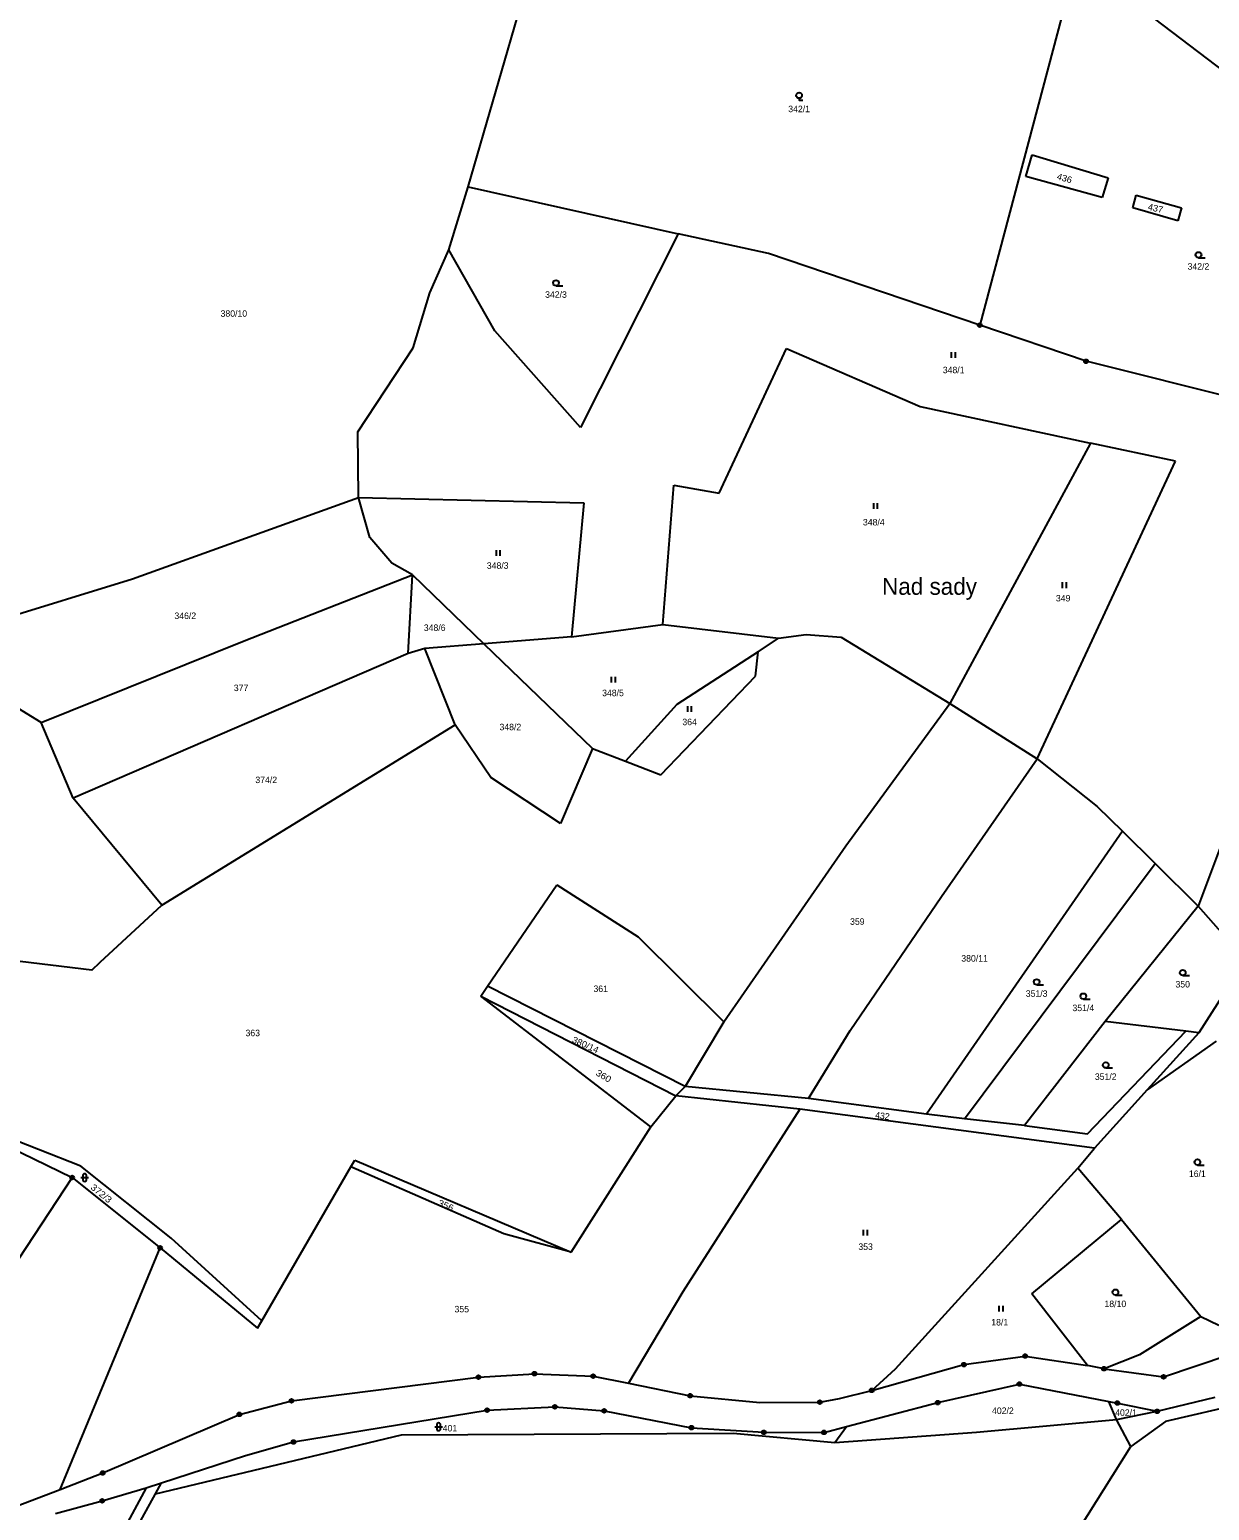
# Model space of a CAD drawing. Extents: x -791548 to -789311, y -1142631 to -1140855.
# Drawn here: x -790753.3 to -790444.3, y -1142346.8 to -1141959 of the extents above; entities that cross this region are included whole.
import ezdxf
from ezdxf.enums import TextEntityAlignment as Align

# ---------------------------------------------------------------- set-up
doc = ezdxf.new("R2010")
doc.units = 0
doc.header["$LTSCALE"] = 0.68
for name, color, linetype, lineweight in [('1', 7, 'Continuous', 25), ('3', 7, 'Continuous', 25), ('7', 7, 'Continuous', 13), ('8', 7, 'Continuous', 25)]:
    doc.layers.add(name, color=color, linetype=linetype, lineweight=lineweight)
doc.layers.add('2', color=7, linetype='Continuous')

msp = doc.modelspace()

# ---------------------------------------------------------------- linework, layer by layer
at = {"layer": '1'}
for p, q in [((-790479.88, -1141943.84), (-790504.47, -1142036.41)), ((-790638.46, -1142000.15), (-790623.72, -1141949.45)), ((-790465.97, -1141950.58), (-790409.55, -1141993.58)), ((-790492.43, -1141997.44), (-790490.72, -1141991.84)), ((-790490.72, -1141991.84), (-790470.82, -1141997.82)), ((-790472.36, -1142003), (-790492.43, -1141997.44)), ((-790470.82, -1141997.82), (-790472.36, -1142003)), ((-790643.5, -1142016.71), (-790638.46, -1142000.15)), ((-790638.46, -1142000.15), (-790583.42, -1142012.45)), ((-790464.34, -1142005.66), (-790463.47, -1142002.34)), ((-790463.47, -1142002.34), (-790451.66, -1142005.71)), ((-790452.58, -1142009.07), (-790464.34, -1142005.66)), ((-790451.66, -1142005.71), (-790452.58, -1142009.07)), ((-790583.42, -1142012.45), (-790609.02, -1142063.22)), ((-790559.75, -1142017.62), (-790583.42, -1142012.45)), ((-790648.46, -1142027.96), (-790643.5, -1142016.71)), ((-790631.41, -1142037.87), (-790643.5, -1142016.71)), ((-790504.47, -1142036.41), (-790559.75, -1142017.62)), ((-790652.8, -1142042.31), (-790648.46, -1142027.96)), ((-790609.02, -1142063.22), (-790631.41, -1142037.87)), ((-790476.62, -1142045.87), (-790504.47, -1142036.41)), ((-790667.36, -1142064.38), (-790652.8, -1142042.31)), ((-790572.66, -1142080.37), (-790555.04, -1142042.51)), ((-790555.04, -1142042.51), (-790520.07, -1142057.67)), ((-790406.17, -1142063.5), (-790476.62, -1142045.87)), ((-790520.07, -1142057.67), (-790475.49, -1142067.34)), ((-790667.17, -1142081.58), (-790667.36, -1142064.38)), ((-790475.49, -1142067.34), (-790512.31, -1142135.46)), ((-790453.23, -1142072.06), (-790475.49, -1142067.34)), ((-790489.4, -1142150.03), (-790453.23, -1142072.06)), ((-790587.41, -1142114.84), (-790584.55, -1142078.32)), ((-790584.55, -1142078.32), (-790572.66, -1142080.37)), ((-790726.36, -1142102.85), (-790667.17, -1142081.58)), ((-790667.17, -1142081.58), (-790608.11, -1142082.9)), ((-790664.16, -1142091.98), (-790667.17, -1142081.58)), ((-790608.11, -1142082.9), (-790611.38, -1142118.03)), ((-790658.38, -1142098.74), (-790664.16, -1142091.98)), ((-790653.02, -1142101.76), (-790658.38, -1142098.74)), ((-790783.03, -1142120.37), (-790726.36, -1142102.85)), ((-790697.06, -1142119.11), (-790653.02, -1142101.76)), ((-790654.16, -1142122.43), (-790653.02, -1142101.76)), ((-790653.02, -1142101.76), (-790634.32, -1142119.84)), ((-790415.68, -1142104.15), (-790447.27, -1142188.54)), ((-790611.38, -1142118.03), (-790587.41, -1142114.84)), ((-790587.41, -1142114.84), (-790557.12, -1142118.38)), ((-790750.26, -1142140.45), (-790697.06, -1142119.11)), ((-790611.38, -1142118.03), (-790634.32, -1142119.84)), ((-790562.48, -1142121.95), (-790557.12, -1142118.38)), ((-790557.12, -1142118.38), (-790549.88, -1142117.43)), ((-790549.88, -1142117.43), (-790540.77, -1142118.16)), ((-790540.77, -1142118.16), (-790512.31, -1142135.46)), ((-790750.26, -1142140.45), (-790783.03, -1142120.37)), ((-790649.81, -1142121.06), (-790654.16, -1142122.43)), ((-790634.32, -1142119.84), (-790649.81, -1142121.06)), ((-790641.86, -1142141.11), (-790649.81, -1142121.06)), ((-790634.32, -1142119.84), (-790605.89, -1142147.32)), ((-790562.48, -1142121.95), (-790583.81, -1142135.76)), ((-790563.14, -1142128.33), (-790562.48, -1142121.95)), ((-790587.98, -1142154.17), (-790563.14, -1142128.33)), ((-790583.81, -1142135.76), (-790597.25, -1142150.63)), ((-790539.56, -1142172.74), (-790512.31, -1142135.46)), ((-790512.31, -1142135.46), (-790489.4, -1142150.03)), ((-790718.67, -1142188.35), (-790641.86, -1142141.11)), ((-790632.48, -1142154.84), (-790641.86, -1142141.11)), ((-790605.89, -1142147.32), (-790614.26, -1142166.93)), ((-790605.89, -1142147.32), (-790597.25, -1142150.63)), ((-790597.25, -1142150.63), (-790587.98, -1142154.17)), ((-790514.44, -1142186.04), (-790489.4, -1142150.03)), ((-790489.4, -1142150.03), (-790473.69, -1142162.44)), ((-790614.26, -1142166.93), (-790632.48, -1142154.84)), ((-790718.67, -1142188.35), (-790741.88, -1142160.32)), ((-790473.69, -1142162.44), (-790467.1, -1142168.97)), ((-790467.1, -1142168.97), (-790518.42, -1142243.08)), ((-790467.1, -1142168.97), (-790458.55, -1142177.45)), ((-790571.45, -1142218.88), (-790539.56, -1142172.74)), ((-790508.49, -1142244.28), (-790458.55, -1142177.45)), ((-790458.55, -1142177.45), (-790447.27, -1142188.54)), ((-790633.36, -1142209.55), (-790615.17, -1142183.02)), ((-790615.17, -1142183.02), (-790593.9, -1142196.62)), ((-790734.82, -1142203.25), (-790718.67, -1142188.35)), ((-790538.38, -1142221.12), (-790514.44, -1142186.04)), ((-790447.27, -1142188.54), (-790471.62, -1142218.81)), ((-790447.27, -1142188.54), (-790434.91, -1142202.65)), ((-790593.9, -1142196.62), (-790571.45, -1142218.88)), ((-790737, -1142205.34), (-790758.58, -1142202.74)), ((-790737, -1142205.34), (-790734.82, -1142203.25)), ((-790434.91, -1142202.65), (-790447.12, -1142221.74)), ((-790635.15, -1142212.17), (-790633.36, -1142209.55)), ((-790635.15, -1142212.17), (-790584.04, -1142238.28)), ((-790590.59, -1142246.41), (-790635.15, -1142212.17)), ((-790581.63, -1142235.79), (-790633.36, -1142209.55)), ((-790571.45, -1142218.88), (-790581.63, -1142235.79)), ((-790471.62, -1142218.81), (-790492.74, -1142246.06)), ((-790450.5, -1142221.34), (-790471.62, -1142218.81)), ((-790549.34, -1142238.94), (-790538.38, -1142221.12)), ((-790476.23, -1142248.24), (-790450.5, -1142221.34)), ((-790447.12, -1142221.74), (-790460.61, -1142236.7)), ((-790442.51, -1142223.96), (-790460.61, -1142236.7)), ((-790447.12, -1142221.74), (-790450.5, -1142221.34)), ((-790584.04, -1142238.28), (-790581.63, -1142235.79)), ((-790549.34, -1142238.94), (-790581.63, -1142235.79)), ((-790590.59, -1142246.41), (-790584.04, -1142238.28)), ((-790551.56, -1142241.78), (-790584.04, -1142238.28)), ((-790518.42, -1142243.08), (-790549.34, -1142238.94)), ((-790460.61, -1142236.7), (-790474.42, -1142252)), ((-790782.18, -1142240.12), (-790742.12, -1142259.66)), ((-790739.85, -1142256.67), (-790782.18, -1142240.12)), ((-790551.56, -1142241.78), (-790582.19, -1142289.58)), ((-790474.42, -1142252), (-790551.56, -1142241.78)), ((-790508.49, -1142244.28), (-790518.42, -1142243.08)), ((-790611.46, -1142279.17), (-790590.59, -1142246.41)), ((-790492.74, -1142246.06), (-790508.49, -1142244.28)), ((-790492.74, -1142246.06), (-790476.23, -1142248.24)), ((-790669.12, -1142256.88), (-790668.1, -1142255.13)), ((-790668.1, -1142255.13), (-790611.46, -1142279.17)), ((-790478.79, -1142257.2), (-790474.42, -1142252)), ((-790716.23, -1142275.52), (-790739.85, -1142256.67)), ((-790692.48, -1142297.17), (-790669.12, -1142256.88)), ((-790629.09, -1142274.43), (-790669.12, -1142256.88)), ((-790526.52, -1142309.76), (-790478.79, -1142257.2)), ((-790467.31, -1142270.67), (-790478.79, -1142257.2)), ((-790742.12, -1142259.66), (-790758.17, -1142284.07)), ((-790742.12, -1142259.66), (-790719.09, -1142278.06)), ((-790490.85, -1142290.09), (-790467.31, -1142270.67)), ((-790467.31, -1142270.67), (-790446.56, -1142296.04)), ((-790611.46, -1142279.17), (-790629.09, -1142274.43)), ((-790745.29, -1142341.37), (-790719.09, -1142278.06)), ((-790719.09, -1142278.06), (-790693.61, -1142299.11)), ((-790692.48, -1142297.17), (-790716.23, -1142275.52)), ((-790582.19, -1142289.58), (-790596.45, -1142313.55)), ((-790476.25, -1142308.91), (-790490.85, -1142290.09)), ((-790693.61, -1142299.11), (-790692.48, -1142297.17)), ((-790446.56, -1142296.04), (-790462.64, -1142306.08)), ((-790446.56, -1142296.04), (-790441.89, -1142298.31)), ((-790532.76, -1142315.4), (-790508.59, -1142308.66)), ((-790532.76, -1142315.4), (-790526.52, -1142309.76)), ((-790508.59, -1142308.66), (-790492.55, -1142306.42)), ((-790492.55, -1142306.42), (-790476.25, -1142308.91)), ((-790471.92, -1142309.74), (-790476.25, -1142308.91)), ((-790462.64, -1142306.08), (-790471.92, -1142309.74)), ((-790471.92, -1142309.74), (-790456.3, -1142311.85)), ((-790456.3, -1142311.85), (-790439.25, -1142306.06)), ((-790684.69, -1142318.16), (-790635.75, -1142311.96)), ((-790635.75, -1142311.96), (-790621.09, -1142311.03)), ((-790621.09, -1142311.03), (-790605.68, -1142311.69)), ((-790605.68, -1142311.69), (-790596.45, -1142313.55)), ((-790596.45, -1142313.55), (-790580.3, -1142316.8)), ((-790580.3, -1142316.8), (-790562.08, -1142318.55)), ((-790546.34, -1142318.5), (-790541.18, -1142317.49)), ((-790541.18, -1142317.49), (-790532.76, -1142315.4)), ((-790515.47, -1142318.6), (-790494.07, -1142313.74)), ((-790494.07, -1142313.74), (-790470.66, -1142318.28)), ((-790457.99, -1142320.89), (-790442.82, -1142317.2)), ((-790698.33, -1142321.69), (-790684.69, -1142318.16)), ((-790684.16, -1142328.92), (-790633.48, -1142320.58)), ((-790633.48, -1142320.58), (-790615.7, -1142319.72)), ((-790615.7, -1142319.72), (-790602.83, -1142320.78)), ((-790602.83, -1142320.78), (-790579.98, -1142325.17)), ((-790562.08, -1142318.55), (-790546.34, -1142318.5)), ((-790539.32, -1142324.85), (-790515.47, -1142318.6)), ((-790468.64, -1142323.01), (-790470.66, -1142318.28)), ((-790470.66, -1142318.28), (-790468.42, -1142318.72)), ((-790468.64, -1142323.01), (-790457.99, -1142320.89)), ((-790468.42, -1142318.72), (-790457.99, -1142320.89)), ((-790431.21, -1142317.88), (-790455.86, -1142323.56)), ((-790734.12, -1142337.02), (-790698.33, -1142321.69)), ((-790579.98, -1142325.17), (-790561.01, -1142326.39)), ((-790545.24, -1142326.41), (-790539.32, -1142324.85)), ((-790542.41, -1142329.04), (-790539.32, -1142324.85)), ((-790505.32, -1142326.36), (-790468.64, -1142323.01)), ((-790464.91, -1142330.08), (-790468.64, -1142323.01)), ((-790455.86, -1142323.56), (-790464.91, -1142330.08)), ((-790720.3, -1142342.48), (-790655.86, -1142327.03)), ((-790696.69, -1142332.46), (-790684.16, -1142328.92)), ((-790655.86, -1142327.03), (-790569.05, -1142326.61)), ((-790569.05, -1142326.61), (-790542.41, -1142329.04)), ((-790561.01, -1142326.39), (-790545.24, -1142326.41)), ((-790542.41, -1142329.04), (-790505.32, -1142326.36)), ((-790718.73, -1142339.65), (-790696.69, -1142332.46)), ((-790484.92, -1142361.93), (-790464.91, -1142330.08)), ((-790745.29, -1142341.37), (-790734.12, -1142337.02)), ((-790722.73, -1142340.96), (-790718.73, -1142339.65)), ((-790720.3, -1142342.48), (-790718.73, -1142339.65)), ((-790758.81, -1142346.48), (-790745.29, -1142341.37)), ((-790746.5, -1142347.69), (-790734.28, -1142344.35)), ((-790722.73, -1142340.96), (-790741.85, -1142376.38)), ((-790739.43, -1142377.07), (-790720.3, -1142342.48)), ((-790734.28, -1142344.35), (-790722.73, -1142340.96))]:
    msp.add_line(p, q, dxfattribs=at)
msp.add_lwpolyline([(-790654.16, -1142122.43), (-790741.88, -1142160.32), (-790750.26, -1142140.45)], dxfattribs=at)
at = {"layer": '3'}
for p, q in [((-790447.183, -1142018.75), (-790445.433, -1142018.75)), ((-790615.423, -1142026.11), (-790613.673, -1142026.11)), ((-790511.841, -1142044.96), (-790511.841, -1142043.46)), ((-790510.84, -1142044.96), (-790510.84, -1142043.46)), ((-790532.221, -1142084.52), (-790532.221, -1142083.02)), ((-790531.22, -1142084.52), (-790531.22, -1142083.02)), ((-790631.041, -1142096.8), (-790631.041, -1142095.3)), ((-790630.04, -1142096.8), (-790630.04, -1142095.3)), ((-790482.761, -1142105.25), (-790482.761, -1142103.75)), ((-790481.76, -1142105.25), (-790481.76, -1142103.75)), ((-790600.851, -1142130.02), (-790600.851, -1142128.52)), ((-790599.85, -1142130.02), (-790599.85, -1142128.52)), ((-790580.911, -1142137.7), (-790580.911, -1142136.2)), ((-790579.91, -1142137.7), (-790579.91, -1142136.2)), ((-790451.303, -1142206.75), (-790449.553, -1142206.75)), ((-790489.553, -1142209.19), (-790487.803, -1142209.19)), ((-790477.333, -1142212.94), (-790475.583, -1142212.94)), ((-790471.463, -1142230.95), (-790469.713, -1142230.95)), ((-790739.351, -1142259.191), (-790739.351, -1142260.192)), ((-790738.349, -1142260.192), (-790738.349, -1142259.191)), ((-790447.473, -1142256.38), (-790445.723, -1142256.38)), ((-790739.851, -1142259.691), (-790737.849, -1142259.691)), ((-790534.891, -1142274.86), (-790534.891, -1142273.36)), ((-790533.89, -1142274.86), (-790533.89, -1142273.36)), ((-790499.351, -1142294.75), (-790499.351, -1142293.25)), ((-790498.35, -1142294.75), (-790498.35, -1142293.25)), ((-790468.943, -1142290.46), (-790467.193, -1142290.46)), ((-790647.161, -1142324.941), (-790645.159, -1142324.941)), ((-790646.661, -1142324.441), (-790646.661, -1142325.442)), ((-790645.659, -1142325.442), (-790645.659, -1142324.441))]:
    msp.add_line(p, q, dxfattribs=at)
msp.add_lwpolyline([(-790551.76, -1141976.992), (-790551.76, -1141977.49), (-790550.759, -1141977.49)], dxfattribs=at)
for centre in [(-790551.7593, -1141976.2409), (-790447.1829, -1142017.9998), (-790615.4229, -1142025.3598), (-790489.5529, -1142208.4398), (-790451.3029, -1142205.9998), (-790477.3329, -1142212.1898), (-790471.4629, -1142230.1998), (-790447.4729, -1142255.6298), (-790468.9429, -1142289.7098)]:
    msp.add_circle(centre, 0.75, dxfattribs=at)
for centre, start, end in [((-790738.85, -1142259.1909), 0, 180), ((-790738.85, -1142260.1909), 180, 359.98789), ((-790646.16, -1142324.4409), 0, 180), ((-790646.16, -1142325.4409), 180, 359.98789)]:
    msp.add_arc(centre, 0.5, start, end, dxfattribs=at)
at = {"layer": '8'}
for centre, radius in [((-790504.47, -1142036.4099), 0.5), ((-790504.47, -1142036.4099), 0.0303), ((-790476.62, -1142045.8699), 0.5), ((-790476.62, -1142045.8699), 0.0303), ((-790742.1199, -1142259.66), 0.5), ((-790742.1199, -1142259.66), 0.0303), ((-790719.0899, -1142278.06), 0.5), ((-790719.0899, -1142278.06), 0.0303), ((-790492.5499, -1142306.42), 0.5), ((-790508.5899, -1142308.66), 0.5), ((-790508.5899, -1142308.66), 0.0303), ((-790492.5499, -1142306.42), 0.0303), ((-790471.9199, -1142309.74), 0.5), ((-790471.9199, -1142309.74), 0.0303), ((-790635.7499, -1142311.96), 0.5), ((-790635.7499, -1142311.96), 0.0303), ((-790621.0899, -1142311.03), 0.5), ((-790621.0899, -1142311.03), 0.0303), ((-790605.6799, -1142311.69), 0.5), ((-790605.6799, -1142311.69), 0.0303), ((-790494.0699, -1142313.74), 0.5), ((-790456.2999, -1142311.85), 0.5), ((-790456.2999, -1142311.85), 0.0303), ((-790580.2999, -1142316.8), 0.5), ((-790580.2999, -1142316.8), 0.0303), ((-790532.7599, -1142315.4), 0.5), ((-790532.7599, -1142315.4), 0.0303), ((-790494.0699, -1142313.74), 0.0303), ((-790698.3299, -1142321.69), 0.5), ((-790684.6899, -1142318.16), 0.5), ((-790684.6899, -1142318.16), 0.0303), ((-790633.4799, -1142320.58), 0.5), ((-790633.4799, -1142320.58), 0.0303), ((-790615.6999, -1142319.72), 0.5), ((-790615.6999, -1142319.72), 0.0303), ((-790602.8299, -1142320.78), 0.5), ((-790602.8299, -1142320.78), 0.0303), ((-790546.3399, -1142318.5), 0.5), ((-790546.3399, -1142318.5), 0.0303), ((-790515.4699, -1142318.6), 0.5), ((-790515.4699, -1142318.6), 0.0303), ((-790468.4199, -1142318.72), 0.5), ((-790468.4199, -1142318.72), 0.0303), ((-790457.9899, -1142320.89), 0.5), ((-790457.9899, -1142320.89), 0.0303), ((-790698.3299, -1142321.69), 0.0303), ((-790579.9799, -1142325.17), 0.5), ((-790579.9799, -1142325.17), 0.0303), ((-790684.1599, -1142328.92), 0.5), ((-790684.1599, -1142328.92), 0.0303), ((-790561.0099, -1142326.39), 0.5), ((-790561.0099, -1142326.39), 0.0303), ((-790545.2399, -1142326.41), 0.5), ((-790545.2399, -1142326.41), 0.0303), ((-790734.1199, -1142337.02), 0.5), ((-790734.1199, -1142337.02), 0.0303), ((-790734.2799, -1142344.35), 0.5), ((-790734.2799, -1142344.35), 0.0303)]:
    msp.add_circle(centre, radius, dxfattribs=at)

# ---------------------------------------------------------------- texts
at = {"layer": '2'}
for s, p in [('342/1', (-790551.76, -1141980.622)), ('342/2', (-790447.19, -1142021.882)), ('342/3', (-790615.43, -1142029.242)), ('380/10', (-790699.78, -1142034.212)), ('348/1', (-790511.29, -1142048.992)), ('348/4', (-790532.2, -1142088.862)), ('348/3', (-790630.69, -1142100.222)), ('349', (-790482.619, -1142108.762)), ('346/2', (-790712.5, -1142113.372)), ('348/6', (-790647.19, -1142116.502)), ('377', (-790697.889, -1142132.252)), ('348/5', (-790600.5, -1142133.582)), ('348/2', (-790627.38, -1142142.502)), ('364', (-790580.439, -1142141.182)), ('374/2', (-790691.3, -1142156.352)), ('359', (-790536.519, -1142193.462)), ('380/11', (-790505.81, -1142203.102)), ('350', (-790451.309, -1142209.882)), ('361', (-790603.719, -1142211.062)), ('351/3', (-790489.56, -1142212.322)), ('351/4', (-790477.34, -1142216.072)), ('363', (-790694.839, -1142222.642)), ('351/2', (-790471.47, -1142234.082)), ('16/1', (-790447.479, -1142259.512)), ('353', (-790534.349, -1142278.612)), ('355', (-790640.099, -1142294.972)), ('18/10', (-790468.95, -1142293.592)), ('18/1', (-790499.229, -1142298.402)), ('402/2', (-790498.4, -1142321.582)), ('402/1', (-790466.15, -1142322.082)), ('401', (-790643.199, -1142326.162))]:
    msp.add_text(s, height=1.7, dxfattribs=at).set_placement(p, align=Align.CENTER)
for s, rotation, width, p in [('436', 344, 1.05, (-790482.4943, -1141998.7363)), ('437', 347, 1.05, (-790458.6112, -1142006.6218)), ('380/14', 336, 1.05, (-790608.0457, -1142225.6791)), ('360', 329, 1.1, (-790603.3878, -1142233.8025)), ('372/3', 321, 1.1, (-790735.0249, -1142264.4971)), ('356', 337, 1.1, (-790644.5911, -1142267.7517))]:
    msp.add_text(s, height=1.7, rotation=rotation, dxfattribs=dict(at, width=width)).set_placement(p, align=Align.CENTER)
msp.add_text('432', height=1.7, rotation=353, dxfattribs=at).set_placement((-790530.0436, -1142244.3389), align=Align.CENTER)
at = {"layer": '7'}
msp.add_text('Nad sady', height=4.4, dxfattribs=at).set_placement((-790530.04, -1142107.03))

doc.saveas('drawing.dxf')
